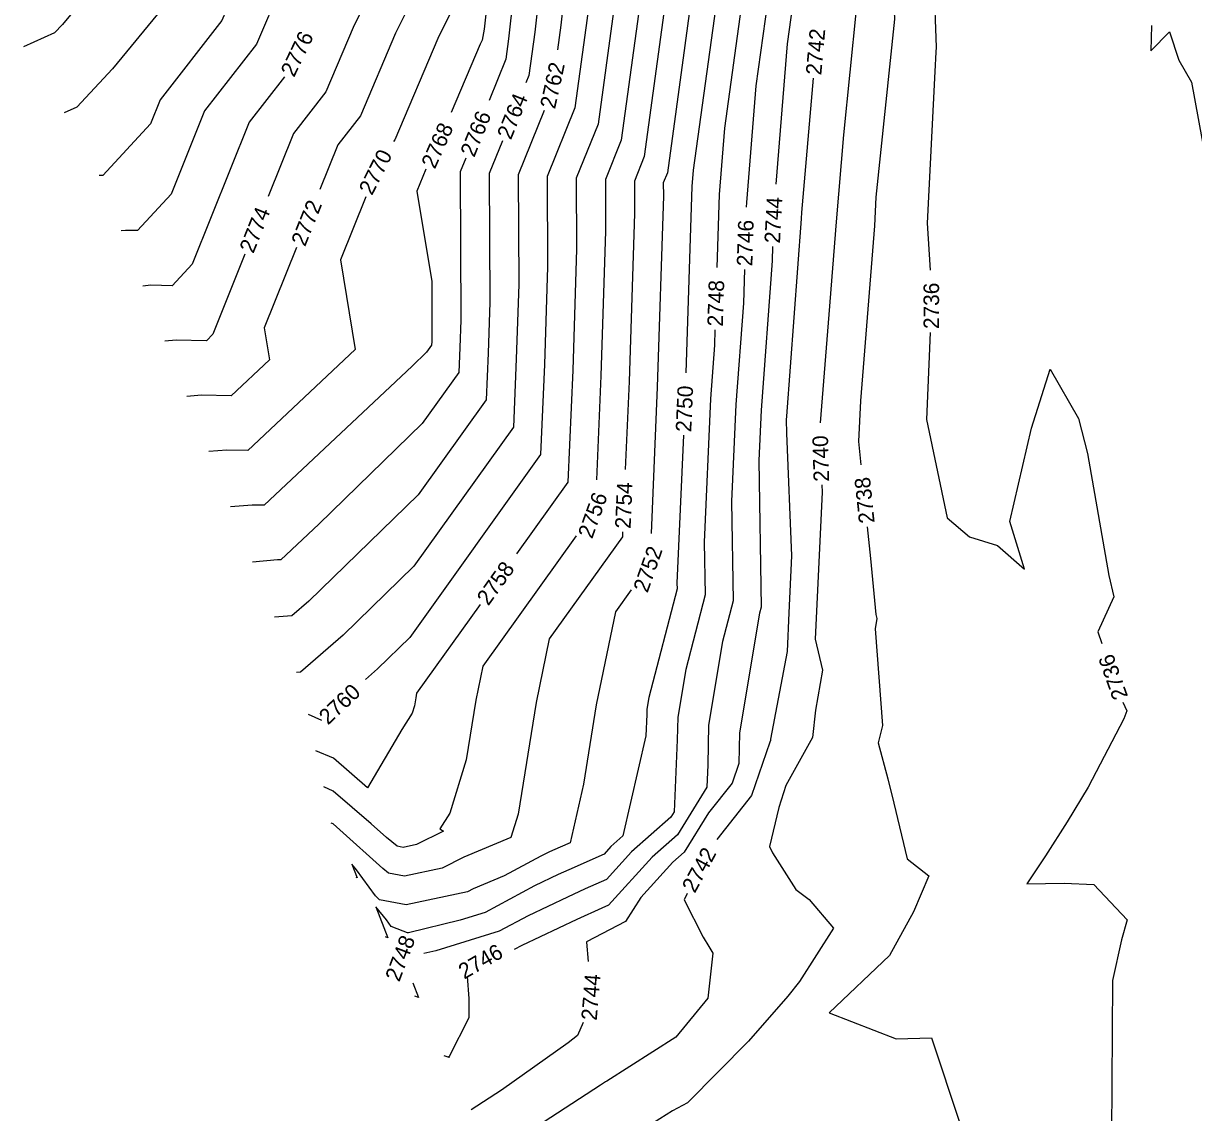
# Model space of a CAD drawing. Extents: x 1326424 to 1329294, y 1001359 to 1003823.
# Drawn here: x 1327580.7 to 1327730.9, y 1002324.7 to 1002464.5 of the extents above; entities that cross this region are included whole.
import ezdxf

# ---------------------------------------------------------------- set-up
doc = ezdxf.new("R2010")
doc.units = 0
doc.layers.add('Prop Rem of Exist Asph Pvmt', color=7, linetype='Continuous')
doc.layers.add('Scratch_Level_3', color=7, linetype='Continuous')

msp = doc.modelspace()

# ---------------------------------------------------------------- linework, layer by layer
at = {"layer": 'Prop Rem of Exist Asph Pvmt'}
for points in [[(1327620.26, 1002512.41), (1327619.46, 1002502.85), (1327619.24, 1002499.83), (1327618.88, 1002496.99), (1327614.95, 1002484.3), (1327608, 1002468.7), (1327606.72, 1002466.13), (1327606.19, 1002464.88), (1327598.27, 1002454.69), (1327597.02, 1002451.58), (1327590.91, 1002444.97), (1327590.56, 1002444.97), (1327590.43, 1002444.96)], [(1327688.98, 1002512.99), (1327689.27, 1002509.64), (1327689.31, 1002501.94), (1327688.53, 1002487.33), (1327687.94, 1002478.73), (1327687.59, 1002466.27), (1327685.98, 1002450.18), (1327685.02, 1002439.04), (1327684.09, 1002427.15), (1327682.96, 1002413.25)], [(1327653.79, 1002471.62), (1327653.07, 1002465.14), (1327651.5, 1002453.65), (1327647.95, 1002444.84), (1327647.99, 1002433.25), (1327647.59, 1002420.73), (1327647.09, 1002409.16), (1327630.3, 1002385.71), (1327626.14, 1002381.67), (1327624.6, 1002380.32)], [(1327683.19, 1002405.26), (1327683.23, 1002404.34), (1327682.44, 1002388.16), (1327682.34, 1002385.49), (1327683.25, 1002381.5), (1327682.37, 1002376.35), (1327681.98, 1002372.85), (1327678.55, 1002366.7), (1327677.66, 1002363.86), (1327676.48, 1002358.87), (1327676.85, 1002358.04), (1327679.85, 1002353.34), (1327681.56, 1002352.07), (1327684.68, 1002348.41), (1327680.31, 1002341.57), (1327678.8, 1002339.66), (1327673.79, 1002333.88), (1327665.94, 1002325.98), (1327664.03, 1002324.95), (1327661.58, 1002323.41), (1327664.74, 1002321.9), (1327665.6, 1002321.61)], [(1327618.99, 1002375.06), (1327617.28, 1002375.8)]]:
    msp.add_lwpolyline(points, dxfattribs=at)
at = {"layer": 'Scratch_Level_3'}
for points in [[(1327644.73, 1002560.03), (1327645.12, 1002558.92), (1327649.83, 1002542.64), (1327650.81, 1002533.29), (1327652.69, 1002517.46), (1327652.62, 1002504.58), (1327651.84, 1002492.6), (1327651.44, 1002479.87), (1327649.7, 1002464.25), (1327649.26, 1002461.08)], [(1327642.84, 1002555.79), (1327643.94, 1002552.6), (1327646.83, 1002542.6), (1327647.43, 1002536.86), (1327649.77, 1002517.26), (1327649.71, 1002507.02), (1327648.75, 1002492.32), (1327648.44, 1002482.28), (1327646.33, 1002463.37), (1327645.57, 1002457.82), (1327645.18, 1002456.84)], [(1327640.36, 1002553.26), (1327642.76, 1002546.29), (1327643.84, 1002542.56), (1327644.06, 1002540.42), (1327646.84, 1002517.07), (1327646.8, 1002509.45), (1327645.67, 1002492.03), (1327645.44, 1002484.69), (1327642.96, 1002462.49), (1327642.61, 1002459.9), (1327640.47, 1002454.6)], [(1327637.67, 1002551.34), (1327640.56, 1002542.94), (1327640.68, 1002542.1), (1327641.41, 1002537.94), (1327643.92, 1002516.88), (1327643.89, 1002511.89), (1327642.58, 1002491.75), (1327642.44, 1002487.1), (1327639.83, 1002463.76), (1327639.59, 1002462.34), (1327639.32, 1002461.81), (1327635.62, 1002453.06)], [(1327635.87, 1002546.85), (1327636.87, 1002543.92), (1327637.28, 1002541.04), (1327639.81, 1002526.63), (1327640.99, 1002516.68), (1327640.98, 1002514.33), (1327639.49, 1002491.46), (1327639.43, 1002489.52), (1327638.34, 1002479.73), (1327636.23, 1002467.21), (1327633.89, 1002462.53), (1327628.4, 1002449.56), (1327628.23, 1002449.35)], [(1327677.24, 1002543.55), (1327680, 1002519.27), (1327680.07, 1002518.66), (1327680.06, 1002518.03), (1327680.63, 1002490.91), (1327680.55, 1002488.52), (1327679.43, 1002466.78), (1327678.75, 1002461.88), (1327677.29, 1002443.85)], [(1327674.47, 1002540.59), (1327676.34, 1002524.16), (1327676.92, 1002518.58), (1327676.88, 1002512.77), (1327677.32, 1002491.55), (1327677.05, 1002483.8), (1327676.2, 1002467.17), (1327674.72, 1002456.47), (1327673.51, 1002441.51), (1327673.49, 1002440.91)], [(1327634.03, 1002539.1), (1327637.93, 1002516.88), (1327637.92, 1002516.51), (1327637.89, 1002516.16), (1327636.09, 1002491.81), (1327635.78, 1002489.33), (1327632.86, 1002472.08), (1327628.46, 1002463.25), (1327623.96, 1002452.63), (1327621.06, 1002448.91), (1327618.76, 1002443.16)], [(1327630.73, 1002537.49), (1327633.73, 1002520.41), (1327633.59, 1002516.51), (1327633.28, 1002512.83), (1327631.88, 1002493.82), (1327630.41, 1002482.38), (1327629.5, 1002476.95), (1327623.02, 1002463.97), (1327619.52, 1002455.69), (1327615.36, 1002450.35), (1327612.12, 1002442.28)], [(1327672.24, 1002532.88), (1327672.67, 1002529.04), (1327673.78, 1002518.5), (1327673.7, 1002507.51), (1327674.02, 1002492.19), (1327673.56, 1002479.09), (1327672.97, 1002467.56), (1327670.7, 1002451.06), (1327670, 1002442.54), (1327669.71, 1002433.18)], [(1327692.24, 1002532.38), (1327693.18, 1002528.2), (1327695.77, 1002513.61), (1327695.94, 1002511.84), (1327696.59, 1002495.53), (1327696.54, 1002494.72), (1327697.37, 1002481.71), (1327697.27, 1002477.89), (1327697.87, 1002461.44), (1327697.8, 1002460.78), (1327697.68, 1002458.31), (1327696.71, 1002438.84), (1327697.07, 1002432.82)], [(1327624.76, 1002530.6), (1327625.31, 1002527.46), (1327624.93, 1002516.5), (1327624.07, 1002506.18), (1327623.45, 1002497.82), (1327622.45, 1002489.98), (1327620.07, 1002482.28), (1327615.85, 1002472.83), (1327612.15, 1002465.41), (1327610.63, 1002461.82), (1327603.97, 1002453.25), (1327599.69, 1002442.59), (1327595.35, 1002437.9), (1327593.81, 1002437.93), (1327593.24, 1002437.88)], [(1327670.53, 1002519.38), (1327670.63, 1002518.42), (1327670.51, 1002502.26), (1327670.71, 1002492.83), (1327670.07, 1002474.38), (1327669.74, 1002467.95), (1327666.67, 1002445.64), (1327666.5, 1002443.58), (1327665.75, 1002419.63)], [(1327614.68, 1002508.51), (1327614.38, 1002505.76), (1327613.99, 1002502.52), (1327609.62, 1002488.38), (1327607.97, 1002485.58), (1327604.97, 1002480.56), (1327598.51, 1002466.38), (1327592.15, 1002458.65), (1327587.57, 1002453.75), (1327585.93, 1002453.02)], [(1327664.33, 1002506.75), (1327664.26, 1002494.84), (1327664.19, 1002493.74), (1327663.45, 1002470.22), (1327663.18, 1002467.78), (1327660.4, 1002447.41), (1327659.12, 1002444.24), (1327659.14, 1002440.08), (1327658.45, 1002418.53), (1327657.96, 1002407.24)], [(1327693.25, 1002507.58), (1327693.41, 1002503.63), (1327692.6, 1002488.07), (1327692.81, 1002484.87), (1327692.36, 1002469.01), (1327692.51, 1002465.02), (1327690.11, 1002442.18), (1327689.94, 1002438.53), (1327688.13, 1002416.07), (1327687.87, 1002410.85), (1327688.18, 1002407.84)], [(1327661.39, 1002505.3), (1327661.35, 1002497.27), (1327661.1, 1002493.46), (1327660.45, 1002472.64), (1327659.81, 1002466.9), (1327657.43, 1002449.49), (1327655.4, 1002444.44), (1327655.42, 1002437.81), (1327654.83, 1002419.26), (1327654.26, 1002405.93)], [(1327667.34, 1002498.67), (1327667.33, 1002497), (1327667.4, 1002493.47), (1327666.58, 1002469.66), (1327666.51, 1002468.34), (1327665.59, 1002461.66), (1327663.36, 1002445.32), (1327662.84, 1002444.04), (1327662.85, 1002442.36), (1327662.06, 1002417.8), (1327661.26, 1002399.03)], [(1327604.5, 1002496.78), (1327604, 1002495.17), (1327598.57, 1002485.92), (1327588.63, 1002469.3), (1327587.17, 1002466.11), (1327585.74, 1002464.36), (1327584.71, 1002463.26), (1327580.71, 1002461.5)], [(1327658.04, 1002493.54), (1327658.01, 1002493.17), (1327657.44, 1002475.05), (1327656.44, 1002466.02), (1327654.47, 1002451.57), (1327651.67, 1002444.64), (1327651.71, 1002435.53), (1327651.21, 1002419.99), (1327650.59, 1002405.64), (1327643.99, 1002396.42)], [(1327725.5, 1002464.22), (1327725.42, 1002460.96), (1327727.79, 1002463.39), (1327728.99, 1002459.75), (1327730.61, 1002456.95), (1327733.35, 1002442), (1327740.27, 1002436.02), (1327741.92, 1002434.08), (1327742.32, 1002427.54), (1327747.82, 1002412.88), (1327748.06, 1002403.86), (1327748.86, 1002390.35), (1327758.85, 1002386.18), (1327760.24, 1002382.64)], [(1327614.21, 1002457.65), (1327609.67, 1002451.8), (1327602.36, 1002433.61), (1327599.79, 1002430.83), (1327597.06, 1002430.88), (1327596.05, 1002430.79)], [(1327682.08, 1002457.46), (1327680.59, 1002440.24), (1327680.52, 1002439.44), (1327680.52, 1002439.41), (1327678.63, 1002414.09), (1327678.61, 1002413.63), (1327678.64, 1002411.9), (1327679.28, 1002396.15), (1327678.93, 1002388.87), (1327678.74, 1002383.89), (1327676.61, 1002372.64), (1327676.59, 1002372.46), (1327676.49, 1002372.26), (1327674.16, 1002365.4), (1327669.69, 1002359.79)], [(1327647.56, 1002453.32), (1327644.23, 1002445.04), (1327644.28, 1002430.98), (1327643.97, 1002421.46), (1327643.6, 1002412.67), (1327630.84, 1002394.86), (1327621.74, 1002386.01), (1327616.27, 1002381.24), (1327615.74, 1002381.2)], [(1327642.19, 1002449.42), (1327640.5, 1002445.24), (1327640.56, 1002428.7), (1327640.35, 1002422.19), (1327640.1, 1002416.18), (1327631.37, 1002404.01), (1327617.34, 1002390.36), (1327615.18, 1002388.48), (1327612.92, 1002388.28)], [(1327637.48, 1002447.18), (1327636.78, 1002445.44), (1327636.85, 1002426.42), (1327636.73, 1002422.92), (1327636.6, 1002419.7), (1327631.91, 1002413.15), (1327618.63, 1002400.25), (1327613.73, 1002395.64), (1327613.33, 1002395.65), (1327610.11, 1002395.37)], [(1327632.36, 1002445.78), (1327631.22, 1002442.94), (1327633.11, 1002431.38), (1327633.13, 1002424.14), (1327633.12, 1002423.66), (1327633.1, 1002423.21), (1327632.45, 1002422.3), (1327630.6, 1002420.51), (1327611.62, 1002402.67), (1327610.08, 1002402.69), (1327607.3, 1002402.45)], [(1327624.67, 1002442.25), (1327621.42, 1002434.17), (1327623.3, 1002422.66), (1327609.5, 1002409.69), (1327606.83, 1002409.74), (1327604.49, 1002409.54)], [(1327676.87, 1002435.87), (1327676.82, 1002434.01), (1327675.38, 1002414.84), (1327675.11, 1002408.39), (1327675.39, 1002389.6), (1327675.19, 1002388.8), (1327672.61, 1002373.45), (1327672.52, 1002369.53), (1327671.66, 1002367.01), (1327668.63, 1002363.2), (1327665.5, 1002358.13), (1327664.05, 1002356.85), (1327659.95, 1002352.32), (1327657.99, 1002349.25), (1327652.97, 1002346.66), (1327652.98, 1002346.61), (1327653.21, 1002344.13)], [(1327609.14, 1002434.86), (1327605.03, 1002424.63), (1327604.23, 1002423.77), (1327600.32, 1002423.83), (1327598.86, 1002423.71)], [(1327615.77, 1002435.74), (1327611.62, 1002425.41), (1327612.29, 1002421.32), (1327607.39, 1002416.72), (1327603.57, 1002416.79), (1327601.68, 1002416.62)], [(1327673.24, 1002432.91), (1327673.11, 1002428.61), (1327672.14, 1002415.58), (1327671.6, 1002403.15), (1327671.8, 1002390.38), (1327670.45, 1002385.19), (1327668.65, 1002374.46), (1327668.54, 1002369.35), (1327668.41, 1002366.48), (1327664.65, 1002360.38), (1327661.4, 1002357.52), (1327655.82, 1002351.36), (1327654.93, 1002350.96), (1327651.74, 1002349.51), (1327644.66, 1002346.16), (1327643.71, 1002345.65)], [(1327669.46, 1002425.18), (1327669.4, 1002423.22), (1327668.89, 1002416.32), (1327668.1, 1002397.91), (1327668.2, 1002391.15), (1327665.72, 1002381.59), (1327664.7, 1002375.48), (1327664.63, 1002372.57), (1327664.22, 1002363.33), (1327663.79, 1002362.64), (1327658.75, 1002358.19), (1327655.53, 1002354.63), (1327652.82, 1002353.42), (1327650.54, 1002352.38), (1327645.49, 1002349.99), (1327641.77, 1002347.99), (1327633.64, 1002345.5), (1327632.11, 1002345.13)], [(1327697.08, 1002424.83), (1327696.62, 1002413.65), (1327699.26, 1002401.04), (1327702.12, 1002398.61), (1327705.75, 1002397.49), (1327709.21, 1002394.46), (1327707.31, 1002400.57), (1327710.11, 1002412.55), (1327712.48, 1002420.12), (1327716.12, 1002413.77), (1327717.3, 1002409.28), (1327720.04, 1002393.65), (1327720.68, 1002390.9), (1327718.62, 1002386.41), (1327719.11, 1002384.94)], [(1327665.41, 1002411.64), (1327664.59, 1002392.67), (1327664.6, 1002391.93), (1327660.99, 1002377.98), (1327660.74, 1002376.5), (1327660.73, 1002375.79), (1327660.6, 1002373.09), (1327657.65, 1002360.22), (1327656.1, 1002358.86), (1327655.25, 1002357.91), (1327650.71, 1002355.88), (1327649.34, 1002355.26), (1327646.31, 1002353.82), (1327639.99, 1002350.42), (1327636.78, 1002349.44), (1327630.14, 1002347.81), (1327630, 1002347.81), (1327629.45, 1002348.03), (1327627.93, 1002348.59), (1327627.29, 1002349.46), (1327625.96, 1002351.12), (1327627.48, 1002347.17), (1327627.18, 1002347.28)], [(1327689.02, 1002399.89), (1327689.45, 1002395.84), (1327690.13, 1002388.66), (1327690.25, 1002388.13), (1327690.02, 1002386.8), (1327690.99, 1002374.4), (1327690.43, 1002372.19), (1327691.67, 1002367.57), (1327692.44, 1002364.42), (1327694.15, 1002357.29), (1327696.93, 1002355.13), (1327694.97, 1002350.5), (1327691.87, 1002344.88), (1327684.12, 1002337.54), (1327692.71, 1002334.19), (1327697.27, 1002334.31), (1327700.93, 1002323.24), (1327700.86, 1002319.07), (1327700.67, 1002317.58)], [(1327651.65, 1002398.72), (1327639.69, 1002382.02), (1327638.78, 1002377.65), (1327637.55, 1002369.98), (1327635.42, 1002363.15), (1327634.14, 1002361.16), (1327634.61, 1002360.83), (1327631.18, 1002359.13), (1327629.43, 1002358.76), (1327628.67, 1002358.91), (1327627.31, 1002360.01), (1327625.34, 1002361.79), (1327620.47, 1002365.98), (1327619.25, 1002366.51)], [(1327657.62, 1002399.24), (1327657.59, 1002398.62), (1327648.2, 1002385.5), (1327646.5, 1002377.34), (1327644.2, 1002363.04), (1327643.27, 1002360.04), (1327637.25, 1002357.49), (1327634.44, 1002356.1), (1327629.63, 1002355.07), (1327627.55, 1002355.47), (1327626.84, 1002356.05), (1327621.32, 1002361.03), (1327620.45, 1002361.78), (1327620.23, 1002361.87)], [(1327658.72, 1002391.79), (1327656.7, 1002388.98), (1327654.23, 1002377.03), (1327652.59, 1002366.86), (1327650.88, 1002359.36), (1327648.6, 1002358.34), (1327648.15, 1002358.13), (1327647.14, 1002357.65), (1327642.41, 1002355.11), (1327638.43, 1002353.42), (1327637.7, 1002353.06), (1327629.82, 1002351.38), (1327626.42, 1002352.04), (1327626.38, 1002352.08), (1327625.88, 1002352.53), (1327623.45, 1002355.86), (1327622.87, 1002356.59), (1327623.53, 1002354.85), (1327623.4, 1002354.9)], [(1327639.33, 1002389.92), (1327631.18, 1002378.55), (1327631.06, 1002377.95), (1327630.89, 1002376.91), (1327630.6, 1002375.99), (1327629.26, 1002373.89), (1327624.89, 1002366.4), (1327620.5, 1002370.19), (1327618.26, 1002371.16)], [(1327721.8, 1002377.41), (1327722.33, 1002376.28), (1327721.96, 1002375.25), (1327717.36, 1002366.48), (1327714.66, 1002362.02), (1327711.89, 1002357.66), (1327709.49, 1002354.1), (1327714.27, 1002354.18), (1327718.08, 1002353.98), (1327722.38, 1002349.45), (1327721.66, 1002346.91), (1327720.47, 1002341.67), (1327720.24, 1002302.16), (1327719.84, 1002300.64), (1327722.11, 1002294.56), (1327721.78, 1002291.93)], [(1327665.92, 1002352.84), (1327665.53, 1002352.05), (1327667.96, 1002347.23), (1327668.67, 1002346.02), (1327669.21, 1002345.19), (1327668.54, 1002339.43), (1327664.44, 1002334.41), (1327655.6, 1002328.76), (1327655.42, 1002328.66), (1327654.77, 1002328.25), (1327641.03, 1002319.32)], [(1327630.7, 1002341.38), (1327631.42, 1002339.49), (1327630.95, 1002339.66)], [(1327637.67, 1002342.18), (1327637.86, 1002339.35), (1327637.87, 1002336.87), (1327635.35, 1002331.94), (1327635.31, 1002331.95), (1327635.37, 1002331.81), (1327634.73, 1002332.03)], [(1327652.56, 1002336.3), (1327651.81, 1002334.62), (1327650.62, 1002333.68), (1327642.06, 1002327.62), (1327638.17, 1002325.09)]]:
    msp.add_lwpolyline(points, dxfattribs=at)

# ---------------------------------------------------------------- texts
at = {"layer": 'Prop Rem of Exist Asph Pvmt'}
for s, rotation, p in [('2740', 91.6023, (1327684.13, 1002405.7)), ('2760', 43.194, (1327619.8, 1002374.39))]:
    msp.add_text(s, height=2, rotation=rotation, dxfattribs=at).set_placement(p)
at = {"layer": 'Scratch_Level_3'}
for s, rotation, p in [('2776', 64.3735, (1327615.44, 1002457.48)), ('2742', 84.9386, (1327683.11, 1002457.79)), ('2762', 77.6193, (1327648.94, 1002453.42)), ('2764', 68.055, (1327643.28, 1002449.45)), ('2766', 68.055, (1327638.57, 1002447.21)), ('2768', 65.9338, (1327633.52, 1002445.71)), ('2770', 63.3536, (1327625.45, 1002442.32)), ('2744', 87.0057, (1327677.81, 1002436.23)), ('2774', 68.1123, (1327610.22, 1002434.87)), ('2772', 68.1123, (1327616.86, 1002435.76)), ('2746', 88.2115, (1327674.26, 1002433.3)), ('2748', 88.2115, (1327670.48, 1002425.57)), ('2736', 90.0658, (1327698.24, 1002425.27)), ('2750', 87.5244, (1327666.42, 1002412.02)), ('2738', 96.0202, (1327689.97, 1002400.44)), ('2756', 70.1277, (1327653.7, 1002398.26)), ('2754', 87.5454, (1327658.64, 1002399.62)), ('2752', 70.6546, (1327660.81, 1002391.33)), ('2758', 54.3855, (1327640.38, 1002389.67)), ('2736', 109.6638, (1327722.51, 1002378.13)), ('2742', 61.5218, (1327666.88, 1002352.79)), ('2748', 69.4356, (1327628.95, 1002341.41)), ('2746', 29.8391, (1327637.29, 1002341.79)), ('2744', 85.2282, (1327654.29, 1002336.5))]:
    msp.add_text(s, height=2, rotation=rotation, dxfattribs=at).set_placement(p)

doc.saveas('drawing.dxf')
